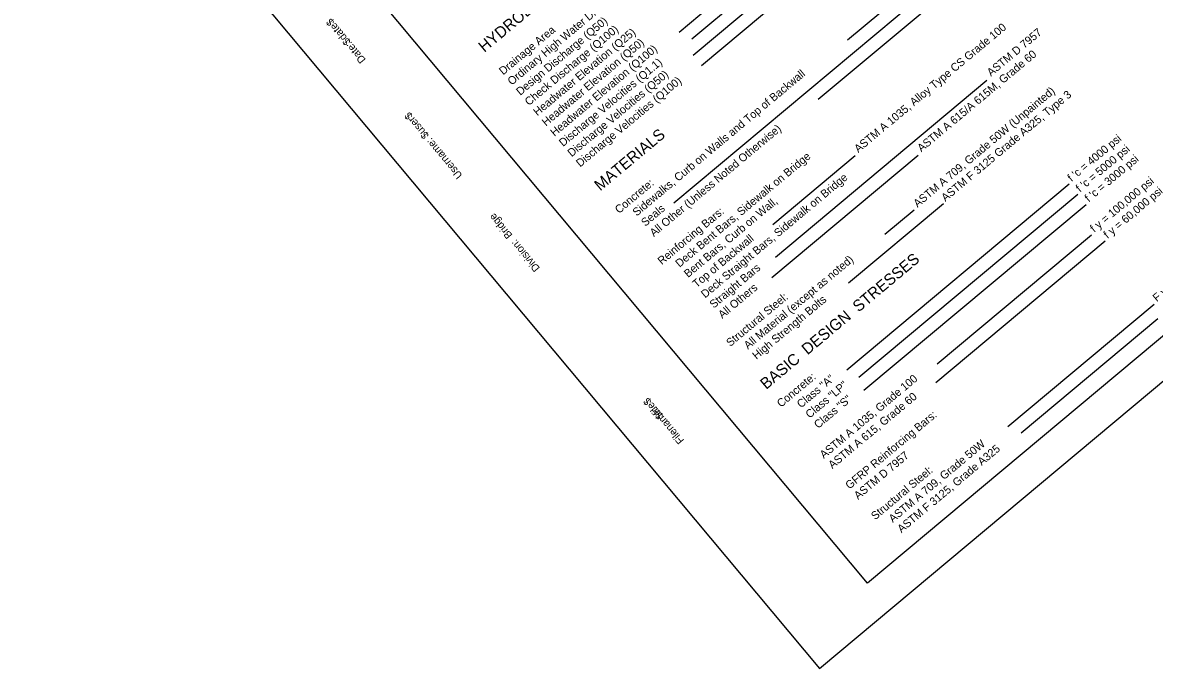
# Model space of a CAD drawing. Extents: x 939471.38 to 939474.73, y 628043.87 to 628047.09.
# Drawn here: x 939471.376 to 939473.046, y 628043.866 to 628044.819 of the extents above; entities that cross this region are included whole.
import ezdxf

# ---------------------------------------------------------------- set-up
doc = ezdxf.new("R2010")
doc.units = 0
for name, color, linetype in [('BORDER', 7, 'Continuous'), ('DIMENSIONS', 7, 'Continuous'), ('PLOT BOUNDARY', 7, 'Continuous')]:
    doc.layers.add(name, color=color, linetype=linetype)

msp = doc.modelspace()

# ---------------------------------------------------------------- linework, layer by layer
at = {"layer": 'BORDER'}
msp.add_lwpolyline([(939471.5003, 628045.334), (939473.546, 628047.0446), (939474.6686, 628045.7022), (939472.6229, 628043.9915)], close=True, dxfattribs=at)
at = {"layer": 'DIMENSIONS'}
for p, q in [((939472.3449, 628044.8047), (939472.6187, 628045.0337)), ((939472.3636, 628044.7947), (939472.6313, 628045.0185)), ((939472.3655, 628044.7706), (939472.6439, 628045.0034)), ((939472.3781, 628044.7555), (939472.6582, 628044.9897)), ((939472.337, 628044.5527), (939472.7278, 628044.8796)), ((939472.5935, 628044.793), (939472.7093, 628044.8897)), ((939472.5504, 628044.7055), (939472.7405, 628044.8645)), ((939472.4871, 628044.4726), (939472.7993, 628044.7337)), ((939472.4818, 628044.4425), (939472.6979, 628044.6233)), ((939472.4832, 628044.5207), (939472.6049, 628044.6225)), ((939472.5926, 628044.3064), (939472.9205, 628044.5806)), ((939472.61, 628044.2953), (939472.9332, 628044.5655)), ((939472.5948, 628044.4345), (939472.735, 628044.5517)), ((939472.6178, 628044.2762), (939472.9458, 628044.5504)), ((939472.6487, 628044.5064), (939472.692, 628044.5426)), ((939472.724, 628044.2877), (939472.9739, 628044.4966)), ((939472.7259, 628044.315), (939472.9535, 628044.5053)), ((939472.83, 628044.2225), (939473.0462, 628044.4033)), ((939472.8498, 628044.2133), (939473.0513, 628044.3819))]:
    msp.add_line(p, q, dxfattribs=at)
at = {"layer": 'PLOT BOUNDARY'}
msp.add_lwpolyline([(939472.5521, 628043.8659), (939474.7257, 628045.6834), (939473.5496, 628047.0898), (939471.3761, 628045.2723)], close=True, dxfattribs=at)

# ---------------------------------------------------------------- texts
at = {"layer": 'BORDER'}
for s, p in [('$date$', (939471.8608, 628044.7908)), ('Date:', (939471.8831, 628044.7641)), ('$user$', (939471.9764, 628044.6526)), ('Username:', (939472.0258, 628044.5935)), ('Bridge', (939472.0996, 628044.5053)), ('Division:', (939472.1402, 628044.4566)), ('$file$', (939472.3224, 628044.2388)), ('Filename:', (939472.3529, 628044.2024))]:
    msp.add_text(s, height=0.01116, rotation=129.9025, dxfattribs=at).set_placement(p)
at = {"layer": 'DIMENSIONS'}
for s, height, p in [('HYDROLOGIC  DATA', 0.016732, (939472.0575, 628044.774)), ('Ordinary High Water Discharge (Q1.1)', 0.011811, (939472.0979, 628044.7256)), ('Design Discharge (Q50)', 0.011811, (939472.1105, 628044.7105)), ('Drainage Area', 0.011811, (939472.0853, 628044.7407)), ('Check Discharge (Q100)', 0.011811, (939472.1232, 628044.6954)), ('Headwater Elevation (Q25)', 0.011811, (939472.1358, 628044.6803)), ('ASTM A 1035, Alloy Type CS Grade 100', 0.011811, (939472.6094, 628044.6262)), ('ASTM D 7957', 0.011811, (939472.8053, 628044.7387)), ('Headwater Elevation (Q50)', 0.011811, (939472.1484, 628044.6652)), ('Headwater Elevation (Q100)', 0.011811, (939472.161, 628044.6501)), ('ASTM A 615/A 615M, Grade 60', 0.011811, (939472.7025, 628044.6271)), ('Discharge Velocities (Q1.1)', 0.011811, (939472.1737, 628044.635)), ('Discharge Velocities (Q50)', 0.011811, (939472.1863, 628044.6199)), ('    Sidewalks, Curb on Walls and Top of Backwall', 0.011811, (939472.2689, 628044.5211)), ('Discharge Velocities (Q100)', 0.011811, (939472.1989, 628044.6048)), ('ASTM A 709, Grade 50W (Unpainted)', 0.011811, (939472.6968, 628044.5453)), ('ASTM F 3125 Grade A325, Type 3', 0.011811, (939472.7379, 628044.554)), ('MATERIALS', 0.01673, (939472.2285, 628044.5695)), ('    All Other (Unless Noted Otherwise)', 0.011811, (939472.2942, 628044.4909)), ("f 'c = 4000 psi", 0.011811, (939472.9242, 628044.5832)), ('    Deck Bent Bars, Sidewalk on Bridge', 0.011811, (939472.3321, 628044.4456)), (" f 'c = 5000 psi", 0.011811, (939472.9332, 628044.565)), ("f 'c = 3000 psi", 0.011811, (939472.9496, 628044.5531)), ('    Deck Straight Bars, Sidewalk on Bridge', 0.011811, (939472.3699, 628044.4003)), ('Concrete:', 0.01181, (939472.2563, 628044.5362)), ('f y = 100,000 psi', 0.011811, (939472.9576, 628044.5084)), ('f y = 60,000 psi', 0.011811, (939472.9773, 628044.4993)), ('    Bent Bars, Curb on Wall,', 0.011811, (939472.3447, 628044.4305)), ('    Seals', 0.01181, (939472.2815, 628044.506)), ('Reinforcing Bars:', 0.011811, (939472.3194, 628044.4607)), ('    Top of Backwall', 0.011811, (939472.3573, 628044.4154)), ('BASIC  DESIGN  STRESSES', 0.016732, (939472.4734, 628044.2766)), ('F y = 50,000 psi', 0.011811, (939473.05, 628044.4061)), ('    Straight Bars', 0.011811, (939472.3826, 628044.3852)), ('    All Material (except as noted)', 0.011811, (939472.4331, 628044.3248)), ('    All Others', 0.011811, (939472.3952, 628044.3701)), ('Structural Steel:', 0.011811, (939472.4205, 628044.3399)), ('    High Strength Bolts', 0.011811, (939472.4457, 628044.3097)), ('Concrete:', 0.01181, (939472.4954, 628044.2503)), ('     Class "A"', 0.011811, (939472.508, 628044.2352)), ('ASTM A 1035, Grade 100', 0.011811, (939472.5586, 628044.1748)), ('     Class "LP"', 0.011811, (939472.5207, 628044.2201)), ('     Class "S"', 0.011811, (939472.5333, 628044.205)), ('ASTM A 615, Grade 60', 0.011811, (939472.5712, 628044.1597)), ('GFRP Reinforcing Bars:', 0.011811, (939472.5964, 628044.1295)), ('    ASTM A 709, Grade 50W', 0.011811, (939472.6469, 628044.0691)), ('    ASTM F 3125, Grade A325', 0.011811, (939472.6596, 628044.054)), ('ASTM D 7957', 0.011811, (939472.6091, 628044.1144)), ('Structural Steel:', 0.011811, (939472.6343, 628044.0842))]:
    msp.add_text(s, height=height, rotation=39.9025, dxfattribs=at).set_placement(p)

doc.saveas('drawing.dxf')
